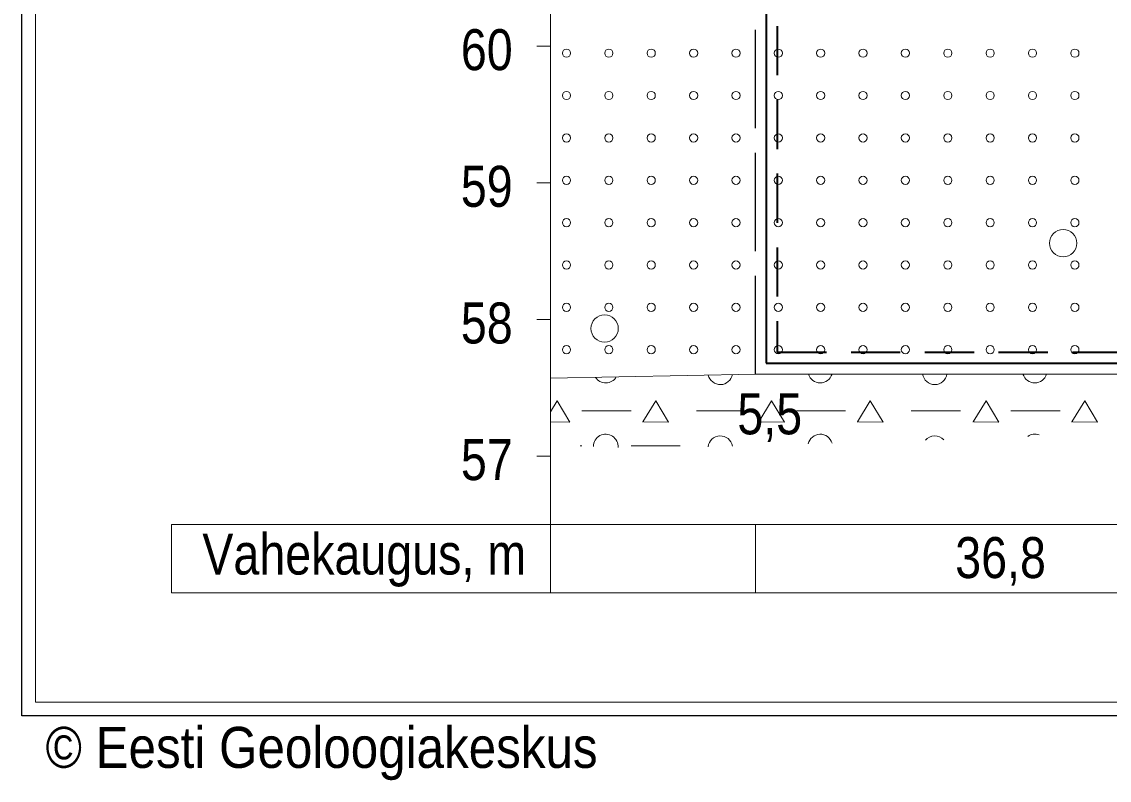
# Model space of a CAD drawing. Extents: x 640121 to 640955, y 6441885 to 6442246.
# Drawn here: x 640121.3 to 640200.9, y 6441884.7 to 6441940.2 of the extents above; entities that cross this region are included whole.
import ezdxf
from ezdxf.enums import TextEntityAlignment as Align

# ---------------------------------------------------------------- set-up
doc = ezdxf.new("R2010")
doc.units = 0
doc.header["$LTSCALE"] = 1.2
doc.linetypes.add('LONG_DASHED', pattern=[7.5, 6, -1.5])
doc.linetypes.add('MEDIUM_DASHED', pattern=[4.5, 3, -1.5])
for name, color, linetype, lineweight in [('30', 7, 'Continuous', 13), ('31', 7, 'Continuous', 13), ('32', 7, 'Continuous', 13), ('35', 7, 'Continuous', 35), ('43', 7, 'Continuous', 13), ('46', 7, 'Continuous', 13), ('47', 7, 'Continuous', 13), ('50', 7, 'Continuous', 13)]:
    doc.layers.add(name, color=color, linetype=linetype, lineweight=lineweight)

msp = doc.modelspace()

# ---------------------------------------------------------------- linework, layer by layer
at = {"layer": '30'}
for p, q in [((640160.01, 6441898.41), (640160.01, 6442028.41)), ((640159.01, 6441938.41), (640160.01, 6441938.41)), ((640159.01, 6441928.41), (640160.01, 6441928.41)), ((640159.01, 6441918.41), (640160.01, 6441918.41)), ((640159.01, 6441908.41), (640160.01, 6441908.41)), ((640175.01, 6441903.41), (640175.01, 6441898.41))]:
    msp.add_line(p, q, dxfattribs=at)
for points in [[(640132.29, 6441898.41), (640465.01, 6441898.41), (640465.01, 6442028.41)], [(640132.29, 6441898.41), (640132.29, 6441903.41), (640465.01, 6441903.41)]]:
    msp.add_lwpolyline(points, dxfattribs=at)
at = {"layer": '31'}
msp.add_lwpolyline([(640160.01, 6441914.1), (640175.01, 6441914.41), (640211.81, 6441914.41), (640262.19, 6441926.41), (640273.21, 6441928.41), (640281.2, 6441928.41), (640286.29, 6441927.68), (640289.79, 6441927.25), (640293.57, 6441926.53), (640298.03, 6441925.47), (640301.11, 6441924.59), (640304.79, 6441923.7)], dxfattribs=at)
at = {"layer": '32', "linetype": 'LONG_DASHED', "lineweight": 25}
msp.add_line((640175.01, 6441914.41), (640175.01, 6441969.45), dxfattribs=at)
at = {"layer": '35', "lineweight": 40}
msp.add_line((640175.81, 6441965.88), (640175.81, 6441915.21), dxfattribs=at)
at = {"layer": '35', "linetype": 'MEDIUM_DASHED'}
msp.add_line((640176.61, 6441950.68), (640176.61, 6441916.01), dxfattribs=at)
msp.add_lwpolyline([(640176.61, 6441916.01), (640211.62, 6441916.01), (640261.86, 6441927.98), (640272.41, 6441929.89)], dxfattribs=at)
at = {"layer": '35', "lineweight": 40}
msp.add_lwpolyline([(640175.81, 6441915.21), (640211.72, 6441915.21), (640262.03, 6441927.19), (640273.14, 6441929.21), (640281.19, 6441929.21)], dxfattribs=at)
at = {"layer": '43'}
for centre in [(640161.188, 6441937.893), (640164.288, 6441937.893), (640167.388, 6441937.893), (640170.488, 6441937.893), (640173.588, 6441937.893), (640176.688, 6441937.893), (640179.788, 6441937.893), (640182.888, 6441937.893), (640185.988, 6441937.893), (640189.088, 6441937.893), (640192.188, 6441937.893), (640195.288, 6441937.893), (640198.388, 6441937.893), (640161.188, 6441934.793), (640164.288, 6441934.793), (640167.388, 6441934.793), (640170.488, 6441934.793), (640173.588, 6441934.793), (640176.688, 6441934.793), (640179.788, 6441934.793), (640182.888, 6441934.793), (640185.988, 6441934.793), (640189.088, 6441934.793), (640192.188, 6441934.793), (640195.288, 6441934.793), (640198.388, 6441934.793), (640161.188, 6441931.693), (640164.288, 6441931.693), (640167.388, 6441931.693), (640170.488, 6441931.693), (640173.588, 6441931.693), (640176.688, 6441931.693), (640179.788, 6441931.693), (640182.888, 6441931.693), (640185.988, 6441931.693), (640189.088, 6441931.693), (640192.188, 6441931.693), (640195.288, 6441931.693), (640198.388, 6441931.693), (640161.188, 6441928.593), (640164.288, 6441928.593), (640167.388, 6441928.593), (640170.488, 6441928.593), (640173.588, 6441928.593), (640176.688, 6441928.593), (640179.788, 6441928.593), (640182.888, 6441928.593), (640185.988, 6441928.593), (640189.088, 6441928.593), (640192.188, 6441928.593), (640195.288, 6441928.593), (640198.388, 6441928.593), (640161.188, 6441925.493), (640164.288, 6441925.493), (640167.388, 6441925.493), (640170.488, 6441925.493), (640173.588, 6441925.493), (640176.688, 6441925.493), (640179.788, 6441925.493), (640182.888, 6441925.493), (640185.988, 6441925.493), (640189.088, 6441925.493), (640192.188, 6441925.493), (640195.288, 6441925.493), (640198.388, 6441925.493), (640161.188, 6441922.393), (640164.288, 6441922.393), (640167.388, 6441922.393), (640170.488, 6441922.393), (640173.588, 6441922.393), (640176.688, 6441922.393), (640179.788, 6441922.393), (640182.888, 6441922.393), (640185.988, 6441922.393), (640189.088, 6441922.393), (640192.188, 6441922.393), (640195.288, 6441922.393), (640198.388, 6441922.393), (640161.188, 6441919.293), (640164.288, 6441919.293), (640167.388, 6441919.293), (640170.488, 6441919.293), (640173.588, 6441919.293), (640176.688, 6441919.293), (640179.788, 6441919.293), (640182.888, 6441919.293), (640185.988, 6441919.293), (640189.088, 6441919.293), (640192.188, 6441919.293), (640195.288, 6441919.293), (640198.388, 6441919.293), (640161.188, 6441916.193), (640164.288, 6441916.193), (640167.388, 6441916.193), (640170.488, 6441916.193), (640173.588, 6441916.193), (640176.688, 6441916.193), (640179.788, 6441916.193), (640182.888, 6441916.193), (640185.988, 6441916.193), (640189.088, 6441916.193), (640192.188, 6441916.193), (640195.288, 6441916.193), (640198.388, 6441916.193)]:
    msp.add_circle(centre, 0.3, dxfattribs=at)
at = {"layer": '46'}
for p, q in [((640165.91, 6441911.72), (640162.31, 6441911.72)), ((640174.31, 6441911.72), (640170.71, 6441911.72)), ((640181.61, 6441911.72), (640178.01, 6441911.72)), ((640190.01, 6441911.72), (640186.41, 6441911.72)), ((640197.3, 6441911.72), (640193.7, 6441911.72)), ((640162.31, 6441909.16), (640162.2, 6441909.16)), ((640169.51, 6441909.16), (640165.91, 6441909.16))]:
    msp.add_line(p, q, dxfattribs=at)
for points in [[(640160.01, 6441911.65), (640160.5, 6441912.44), (640161.43, 6441910.9), (640160.01, 6441910.91)], [(640166.77, 6441910.89), (640166.78, 6441910.91), (640167.72, 6441912.44), (640168.65, 6441910.9), (640166.85, 6441910.91)], [(640175.25, 6441910.89), (640175.25, 6441910.91), (640176.2, 6441912.44), (640177.13, 6441910.9), (640175.33, 6441910.91)], [(640182.47, 6441910.89), (640182.47, 6441910.91), (640183.42, 6441912.44), (640184.35, 6441910.9), (640182.55, 6441910.91)], [(640190.94, 6441910.89), (640190.94, 6441910.91), (640191.89, 6441912.44), (640192.82, 6441910.9), (640191.02, 6441910.91)], [(640198.16, 6441910.89), (640198.17, 6441910.91), (640199.11, 6441912.44), (640200.04, 6441910.9), (640198.24, 6441910.91)]]:
    msp.add_lwpolyline(points, dxfattribs=at)
for centre, start, end in [((640164.06, 6441914.664), 213.20845, 329.12103), ((640172.442, 6441914.542), 193.02606, 349.30342), ((640179.755, 6441914.664), 196.45695, 343.54305), ((640188.137, 6441914.542), 188.48564, 351.51436), ((640195.45, 6441914.664), 196.45695, 343.54305), ((640164.06, 6441909.11), 355.63806, 179.38284), ((640172.442, 6441908.988), 9.65106, 173.82035), ((640179.755, 6441909.11), 16.10414, 167.36727), ((640188.137, 6441908.988), 43.48907, 139.98234), ((640195.45, 6441909.11), 69.71146, 124.53858)]:
    msp.add_arc(centre, 0.9, start, end, dxfattribs=at)
at = {"layer": '47'}
for centre in [(640197.532, 6441923.991), (640163.981, 6441917.749)]:
    msp.add_circle(centre, 1, dxfattribs=at)
at = {"layer": '50', "lineweight": 25}
msp.add_lwpolyline([(640121.33, 6442246.16), (640955.23, 6442246.16), (640955.23, 6441889.4), (640121.33, 6441889.4)], close=True, dxfattribs=at)
at = {"layer": '50'}
msp.add_lwpolyline([(640122.33, 6442245.16), (640954.23, 6442245.16), (640954.23, 6441890.4), (640122.33, 6441890.4)], close=True, dxfattribs=at)

# ---------------------------------------------------------------- texts
at = {"layer": '30', "width": 0.85}
for s, p in [('60', (640155.355, 6441936.65)), ('59', (640155.355, 6441926.65)), ('58', (640155.355, 6441916.65)), ('57', (640155.36, 6441906.65)), ('Vahekaugus, m', (640146.39, 6441899.74)), ('36,8', (640192.95, 6441899.48))]:
    msp.add_text(s, height=3, dxfattribs=at).set_placement(p, align=Align.CENTER)
at = {"layer": '32', "width": 0.85}
msp.add_text('5,5', height=3, dxfattribs=at).set_placement((640176.06, 6441910), align=Align.CENTER)
at = {"layer": '50', "width": 0.9}
msp.add_text('© Eesti Geoloogiakeskus', height=3, dxfattribs=at).set_placement((640143.27, 6441885.59), align=Align.CENTER)

doc.saveas('drawing.dxf')
